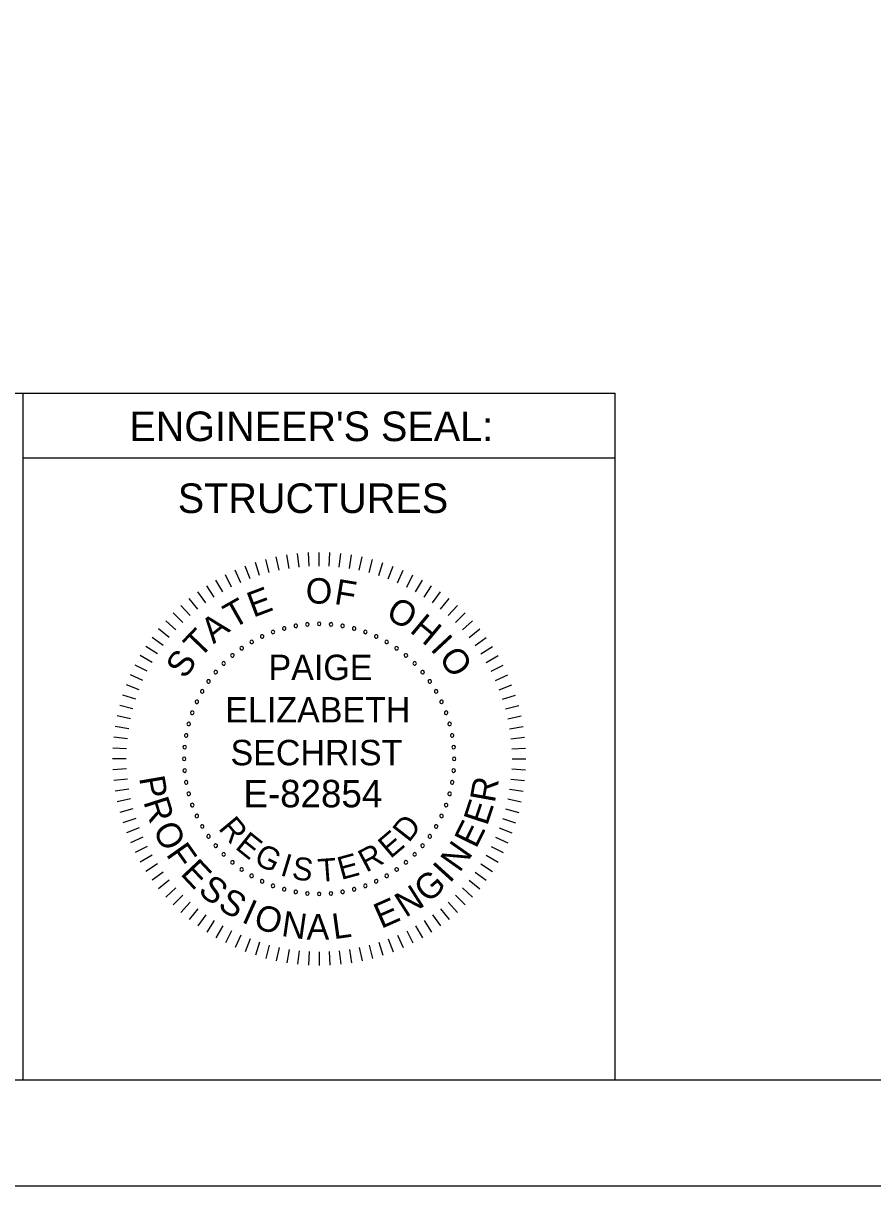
# Model space of a CAD drawing. Extents: x -13.1 to 43.1, y 0 to 22.
# Drawn here: x 27.81 to 31.83, y 0 to 5.5 of the extents above; entities that cross this region are included whole.
import ezdxf

# ---------------------------------------------------------------- set-up
doc = ezdxf.new("R2010")
doc.units = 0
for name, color, linetype in [('SEAL', 7, 'Continuous'), ('SH_Border', 7, 'Continuous'), ('SH_Data', 7, 'Continuous'), ('SH_Text', 7, 'Continuous')]:
    doc.layers.add(name, color=color, linetype=linetype)

msp = doc.modelspace()

# ---------------------------------------------------------------- linework, layer by layer
at = {"layer": 'SEAL'}
for p, q in [((29.0251, 2.9121), (29.0117, 2.9754)), ((29.0721, 2.9208), (29.062, 2.9847)), ((29.1195, 2.927), (29.1127, 2.9914)), ((29.1671, 2.9308), (29.1637, 2.9954)), ((29.2148, 2.932), (29.2148, 2.9967)), ((29.2626, 2.9308), (29.266, 2.9954)), ((29.3102, 2.927), (29.317, 2.9914)), ((29.3576, 2.9208), (29.3677, 2.9847)), ((29.4045, 2.9121), (29.418, 2.9754)), ((28.8878, 2.8714), (28.8647, 2.9318)), ((28.9329, 2.8874), (28.9129, 2.9489)), ((28.9787, 2.9009), (28.9619, 2.9634)), ((29.451, 2.9009), (29.4677, 2.9634)), ((29.4968, 2.8874), (29.5168, 2.9489)), ((29.5418, 2.8714), (29.565, 2.9318)), ((28.7586, 2.8098), (28.7263, 2.8658)), ((28.8006, 2.8326), (28.7712, 2.8902)), ((28.8437, 2.8531), (28.8174, 2.9123)), ((29.586, 2.8531), (29.6123, 2.9123)), ((29.6291, 2.8326), (29.6584, 2.8902)), ((29.6711, 2.8098), (29.7034, 2.8658)), ((28.6785, 2.7578), (28.6405, 2.8101)), ((28.7179, 2.7848), (28.6826, 2.8391)), ((29.7118, 2.7848), (29.747, 2.8391)), ((29.7512, 2.7578), (29.7892, 2.8101)), ((28.6406, 2.7287), (28.5999, 2.779)), ((29.789, 2.7287), (29.8298, 2.779)), ((28.5696, 2.6648), (28.5239, 2.7105)), ((28.6043, 2.6977), (28.561, 2.7458)), ((29.8254, 2.6977), (29.8687, 2.7458)), ((29.86, 2.6648), (29.9058, 2.7105)), ((28.5368, 2.6301), (28.4887, 2.6734)), ((29.8929, 2.6301), (29.941, 2.6734)), ((28.4767, 2.5559), (28.4243, 2.5939)), ((28.5057, 2.5938), (28.4554, 2.6345)), ((29.9239, 2.5938), (29.9742, 2.6345)), ((29.953, 2.5559), (30.0054, 2.5939)), ((28.4496, 2.5165), (28.3953, 2.5518)), ((29.9801, 2.5165), (30.0343, 2.5518)), ((28.4246, 2.4758), (28.3686, 2.5082)), ((30.005, 2.4758), (30.0611, 2.5082)), ((28.4018, 2.4338), (28.3442, 2.4632)), ((30.0278, 2.4338), (30.0855, 2.4632)), ((28.363, 2.3466), (28.3026, 2.3698)), ((28.3813, 2.3907), (28.3222, 2.417)), ((30.0484, 2.3907), (30.1075, 2.417)), ((30.0667, 2.3466), (30.1271, 2.3698)), ((28.347, 2.3016), (28.2855, 2.3215)), ((30.0826, 2.3016), (30.1442, 2.3215)), ((28.3335, 2.2557), (28.271, 2.2725)), ((30.0962, 2.2557), (30.1587, 2.2725)), ((28.3223, 2.2093), (28.259, 2.2228)), ((30.1073, 2.2093), (30.1706, 2.2228)), ((28.3136, 2.1623), (28.2497, 2.1725)), ((30.116, 2.1623), (30.1799, 2.1725)), ((28.3074, 2.115), (28.243, 2.1217)), ((30.1223, 2.115), (30.1866, 2.1217)), ((28.3036, 2.0673), (28.239, 2.0707)), ((30.126, 2.0673), (30.1906, 2.0707)), ((28.3024, 2.0196), (28.2377, 2.0196)), ((30.1273, 2.0196), (30.192, 2.0196)), ((28.3036, 1.9718), (28.239, 1.9685)), ((30.126, 1.9718), (30.1906, 1.9685)), ((28.3074, 1.9242), (28.243, 1.9175)), ((28.3136, 1.8769), (28.2497, 1.8667)), ((30.116, 1.8769), (30.1799, 1.8667)), ((30.1223, 1.9242), (30.1866, 1.9175)), ((28.3223, 1.8299), (28.259, 1.8164)), ((30.1073, 1.8299), (30.1706, 1.8164)), ((28.3335, 1.7834), (28.271, 1.7667)), ((30.0962, 1.7834), (30.1587, 1.7667)), ((28.347, 1.7376), (28.2855, 1.7176)), ((30.0826, 1.7376), (30.1442, 1.7176)), ((28.363, 1.6926), (28.3026, 1.6694)), ((30.0667, 1.6926), (30.1271, 1.6694)), ((28.3813, 1.6485), (28.3222, 1.6222)), ((28.4018, 1.6054), (28.3442, 1.576)), ((30.0278, 1.6054), (30.0855, 1.576)), ((30.0484, 1.6485), (30.1075, 1.6222)), ((28.4246, 1.5634), (28.3686, 1.531)), ((30.005, 1.5634), (30.0611, 1.531)), ((28.4496, 1.5226), (28.3953, 1.4874)), ((29.9801, 1.5226), (30.0343, 1.4874)), ((28.4767, 1.4833), (28.4243, 1.4452)), ((28.5057, 1.4454), (28.4554, 1.4047)), ((29.9239, 1.4454), (29.9742, 1.4047)), ((29.953, 1.4833), (30.0054, 1.4452)), ((28.5368, 1.4091), (28.4887, 1.3658)), ((29.8929, 1.4091), (29.941, 1.3658)), ((28.5696, 1.3744), (28.5239, 1.3286)), ((28.6043, 1.3415), (28.561, 1.2934)), ((29.8254, 1.3415), (29.8687, 1.2934)), ((29.86, 1.3744), (29.9058, 1.3286)), ((28.6406, 1.3105), (28.5999, 1.2602)), ((28.6785, 1.2814), (28.6405, 1.2291)), ((29.7512, 1.2814), (29.7892, 1.2291)), ((29.789, 1.3105), (29.8298, 1.2602)), ((28.7179, 1.2544), (28.6826, 1.2001)), ((28.7586, 1.2294), (28.7263, 1.1734)), ((29.6711, 1.2294), (29.7034, 1.1734)), ((29.7118, 1.2544), (29.747, 1.2001)), ((28.8006, 1.2066), (28.7712, 1.1489)), ((28.8437, 1.186), (28.8174, 1.1269)), ((28.8878, 1.1678), (28.8647, 1.1073)), ((29.5418, 1.1678), (29.565, 1.1073)), ((29.586, 1.186), (29.6123, 1.1269)), ((29.6291, 1.2066), (29.6584, 1.1489)), ((28.9329, 1.1518), (28.9129, 1.0903)), ((28.9787, 1.1382), (28.9619, 1.0757)), ((29.0251, 1.1271), (29.0117, 1.0638)), ((29.0721, 1.1184), (29.062, 1.0545)), ((29.1195, 1.1122), (29.1127, 1.0478)), ((29.1671, 1.1084), (29.1637, 1.0438)), ((29.2148, 1.1072), (29.2148, 1.0424)), ((29.2626, 1.1084), (29.266, 1.0438)), ((29.3102, 1.1122), (29.317, 1.0478)), ((29.3576, 1.1184), (29.3677, 1.0545)), ((29.4045, 1.1271), (29.418, 1.0638)), ((29.451, 1.1382), (29.4677, 1.0757)), ((29.4968, 1.1518), (29.5168, 1.0903))]:
    msp.add_line(p, q, dxfattribs=at)
for centre, start, end in [((29.0495, 2.6367), 15, 195), ((29.1039, 2.6488), 10, 190), ((29.1039, 2.6488), 190, 10), ((29.1591, 2.6561), 5, 185), ((29.1591, 2.6561), 185, 5), ((29.2148, 2.6585), 0, 180), ((29.2148, 2.6585), 180, 0), ((29.2705, 2.6561), 355, 175), ((29.2705, 2.6561), 175, 355), ((29.3258, 2.6488), 170, 350), ((29.3258, 2.6488), 350, 170), ((29.3802, 2.6367), 345, 165), ((28.9448, 2.5986), 25, 205), ((28.9448, 2.5986), 205, 25), ((28.9963, 2.62), 20, 200), ((28.9963, 2.62), 200, 20), ((29.0495, 2.6367), 195, 15), ((29.3802, 2.6367), 165, 345), ((29.4333, 2.62), 160, 340), ((29.4333, 2.62), 340, 160), ((29.4848, 2.5986), 155, 335), ((29.4848, 2.5986), 335, 155), ((28.8484, 2.543), 35, 215), ((28.8484, 2.543), 215, 35), ((28.8954, 2.5729), 30, 210), ((28.8954, 2.5729), 210, 30), ((29.5343, 2.5729), 150, 330), ((29.5343, 2.5729), 330, 150), ((29.5813, 2.543), 145, 325), ((29.5813, 2.543), 325, 145), ((28.7631, 2.4714), 45, 225), ((28.7631, 2.4714), 225, 45), ((28.8042, 2.509), 40, 220), ((28.8042, 2.509), 220, 40), ((29.6255, 2.509), 140, 320), ((29.6255, 2.509), 320, 140), ((29.6666, 2.4714), 135, 315), ((29.6666, 2.4714), 315, 135), ((28.7254, 2.4303), 50, 230), ((28.7254, 2.4303), 230, 50), ((29.7043, 2.4303), 130, 310), ((29.7043, 2.4303), 310, 130), ((28.6915, 2.3861), 55, 235), ((28.6915, 2.3861), 235, 55), ((29.7382, 2.3861), 125, 305), ((29.7382, 2.3861), 305, 125), ((28.6615, 2.339), 60, 240), ((28.6615, 2.339), 240, 60), ((29.7681, 2.339), 120, 300), ((29.7681, 2.339), 300, 120), ((28.6358, 2.2896), 65, 245), ((28.6358, 2.2896), 245, 65), ((29.7939, 2.2896), 115, 295), ((29.7939, 2.2896), 295, 115), ((28.6145, 2.2381), 70, 250), ((28.6145, 2.2381), 250, 70), ((29.8152, 2.2381), 110, 290), ((29.8152, 2.2381), 290, 110), ((28.5977, 2.185), 75, 255), ((28.5977, 2.185), 255, 75), ((29.832, 2.185), 105, 285), ((29.832, 2.185), 285, 105), ((28.5856, 2.1305), 80, 260), ((28.5856, 2.1305), 260, 80), ((29.844, 2.1305), 100, 280), ((29.844, 2.1305), 280, 100), ((28.5784, 2.0753), 85, 265), ((28.5784, 2.0753), 265, 85), ((29.8513, 2.0753), 95, 275), ((29.8513, 2.0753), 275, 95), ((28.5759, 2.0196), 90, 270), ((28.5759, 2.0196), 270, 90), ((29.8537, 2.0196), 90, 270), ((29.8537, 2.0196), 270, 90), ((28.5784, 1.9639), 95, 275), ((28.5784, 1.9639), 275, 95), ((29.8513, 1.9639), 85, 265), ((29.8513, 1.9639), 265, 85), ((28.5856, 1.9086), 100, 280), ((28.5856, 1.9086), 280, 100), ((29.844, 1.9086), 80, 260), ((29.844, 1.9086), 260, 80), ((28.5977, 1.8542), 105, 285), ((28.5977, 1.8542), 285, 105), ((29.832, 1.8542), 75, 255), ((29.832, 1.8542), 255, 75), ((28.6145, 1.8011), 110, 290), ((28.6145, 1.8011), 290, 110), ((29.8152, 1.8011), 70, 250), ((29.8152, 1.8011), 250, 70), ((28.6358, 1.7496), 115, 295), ((28.6358, 1.7496), 295, 115), ((28.6615, 1.7001), 120, 300), ((28.6615, 1.7001), 300, 120), ((29.7681, 1.7001), 60, 240), ((29.7681, 1.7001), 240, 60), ((29.7939, 1.7496), 65, 245), ((29.7939, 1.7496), 245, 65), ((28.6915, 1.6531), 125, 305), ((28.6915, 1.6531), 305, 125), ((29.7382, 1.6531), 55, 235), ((29.7382, 1.6531), 235, 55), ((28.7254, 1.6089), 130, 310), ((28.7254, 1.6089), 310, 130), ((29.7043, 1.6089), 50, 230), ((29.7043, 1.6089), 230, 50), ((28.7631, 1.5678), 135, 315), ((28.7631, 1.5678), 315, 135), ((29.6666, 1.5678), 45, 225), ((29.6666, 1.5678), 225, 45), ((28.8042, 1.5302), 140, 320), ((28.8042, 1.5302), 320, 140), ((28.8484, 1.4962), 145, 325), ((28.8484, 1.4962), 325, 145), ((29.5813, 1.4962), 35, 215), ((29.5813, 1.4962), 215, 35), ((29.6255, 1.5302), 40, 220), ((29.6255, 1.5302), 220, 40), ((28.8954, 1.4663), 150, 330), ((28.8954, 1.4663), 330, 150), ((28.9448, 1.4405), 155, 335), ((28.9448, 1.4405), 335, 155), ((29.4848, 1.4405), 25, 205), ((29.4848, 1.4405), 205, 25), ((29.5343, 1.4663), 30, 210), ((29.5343, 1.4663), 210, 30), ((28.9963, 1.4192), 160, 340), ((28.9963, 1.4192), 340, 160), ((29.0495, 1.4025), 165, 345), ((29.0495, 1.4025), 345, 165), ((29.1039, 1.3904), 170, 350), ((29.1039, 1.3904), 350, 170), ((29.1591, 1.3831), 355, 175), ((29.1591, 1.3831), 175, 355), ((29.2148, 1.3807), 0, 180), ((29.2148, 1.3807), 180, 0), ((29.2705, 1.3831), 5, 185), ((29.2705, 1.3831), 185, 5), ((29.3258, 1.3904), 10, 190), ((29.3258, 1.3904), 190, 10), ((29.3802, 1.4025), 15, 195), ((29.3802, 1.4025), 195, 15), ((29.4333, 1.4192), 20, 200), ((29.4333, 1.4192), 200, 20)]:
    msp.add_arc(centre, 0.00826, start, end, dxfattribs=at)
at = {"layer": 'SH_Border'}
msp.add_lwpolyline([(1.5, 21.5), (33.5, 21.5), (33.5, 0.5), (1.5, 0.5)], close=True, dxfattribs=at)
at = {"layer": 'SH_Data'}
for p, q in [((25.0148, 3.75), (30.6148, 3.75)), ((27.8148, 0.5), (27.8148, 3.75)), ((30.6148, 0.5), (30.6148, 3.75)), ((27.8148, 3.4444), (30.6148, 3.4444))]:
    msp.add_line(p, q, dxfattribs=at)
msp.add_lwpolyline([(0, 0), (34, 0), (34, 22), (0, 22)], close=True, dxfattribs=at)

# ---------------------------------------------------------------- texts
at = {"layer": 'SEAL'}
for s, height, rotation, p in [('O', 0.1203, 359.8493, (29.1514, 2.7544)), ('F', 0.1203, 350.7398, (29.2824, 2.7529)), ('E', 0.1203, 20.6845, (28.9029, 2.6871)), ('T', 0.1203, 29.5936, (28.8074, 2.6331)), ('O', 0.1203, 330.1051, (29.5243, 2.6891)), ('H', 0.1203, 320.1903, (29.6386, 2.6228)), ('T', 0.1203, 46.1424, (28.6495, 2.4916)), ('A', 0.1203, 38.3407, (28.7152, 2.561)), ('I', 0.1203, 312.9395, (29.7368, 2.5371)), ('S', 0.1203, 55.1599, (28.5799, 2.3933)), ('O', 0.1203, 305.2495, (29.7771, 2.4969)), ('P', 0.1203, 279.7454, (28.3628, 1.9301)), ('R', 0.1203, 79.7806, (30.0454, 1.8082)), ('R', 0.1203, 287.7472, (28.3821, 1.8168)), ('E', 0.1203, 71.7788, (30.0094, 1.6991)), ('O', 0.1203, 297.2934, (28.4251, 1.6856)), ('R', 0.1082, 309.8787, (28.7343, 1.6893)), ('D', 0.1082, 52.0798, (29.6392, 1.6198)), ('E', 0.1203, 63.7771, (29.957, 1.5916)), ('E', 0.1082, 321.3329, (28.8128, 1.5978)), ('E', 0.1082, 40.3546, (29.5523, 1.5446)), ('F', 0.1203, 305.2951, (28.4874, 1.5675)), ('G', 0.1082, 333.1405, (28.9001, 1.5283)), ('R', 0.1082, 27.8019, (29.4373, 1.4806)), ('N', 0.1203, 54.8716, (29.8791, 1.478)), ('E', 0.1203, 313.2969, (28.5542, 1.4741)), ('I', 0.1082, 343.0856, (29.0258, 1.4703)), ('S', 0.1082, 351.7916, (29.082, 1.4522)), ('T', 0.1082, 4.3443, (29.2128, 1.4372)), ('E', 0.1082, 15.2492, (29.3189, 1.4463)), ('I', 0.1203, 47.7736, (29.8322, 1.4278)), ('S', 0.1203, 321.2986, (28.6366, 1.3874)), ('G', 0.1203, 41.2489, (29.7294, 1.3337)), ('S', 0.1203, 329.3004, (28.7302, 1.3131)), ('N', 0.1203, 32.5477, (29.6236, 1.2663)), ('I', 0.1203, 335.7577, (28.8425, 1.2496)), ('O', 0.1203, 342.7173, (28.8985, 1.2227)), ('E', 0.1203, 23.7683, (29.5081, 1.2146)), ('N', 0.1203, 351.7612, (29.0323, 1.1822)), ('A', 0.1203, 359.763, (29.1553, 1.1649)), ('L', 0.1203, 7.7648, (29.284, 1.1662))]:
    msp.add_text(s, height=height, rotation=rotation, dxfattribs=at).set_placement(p)
for s, height, p in [('PAIGE', 0.12026, (28.9752, 2.3923)), ('ELIZABETH', 0.12026, (28.7707, 2.1919)), ('SECHRIST', 0.12026, (28.7954, 1.9893)), ('E-82854', 0.12989, (28.8566, 1.7904))]:
    msp.add_text(s, height=height, dxfattribs=at).set_placement(p)
at = {"layer": 'SH_Text'}
for s, p in [("ENGINEER'S SEAL:", (28.3168, 3.523)), ('STRUCTURES', (28.5459, 3.1828))]:
    msp.add_text(s, height=0.14, dxfattribs=at).set_placement(p)

doc.saveas('drawing.dxf')
